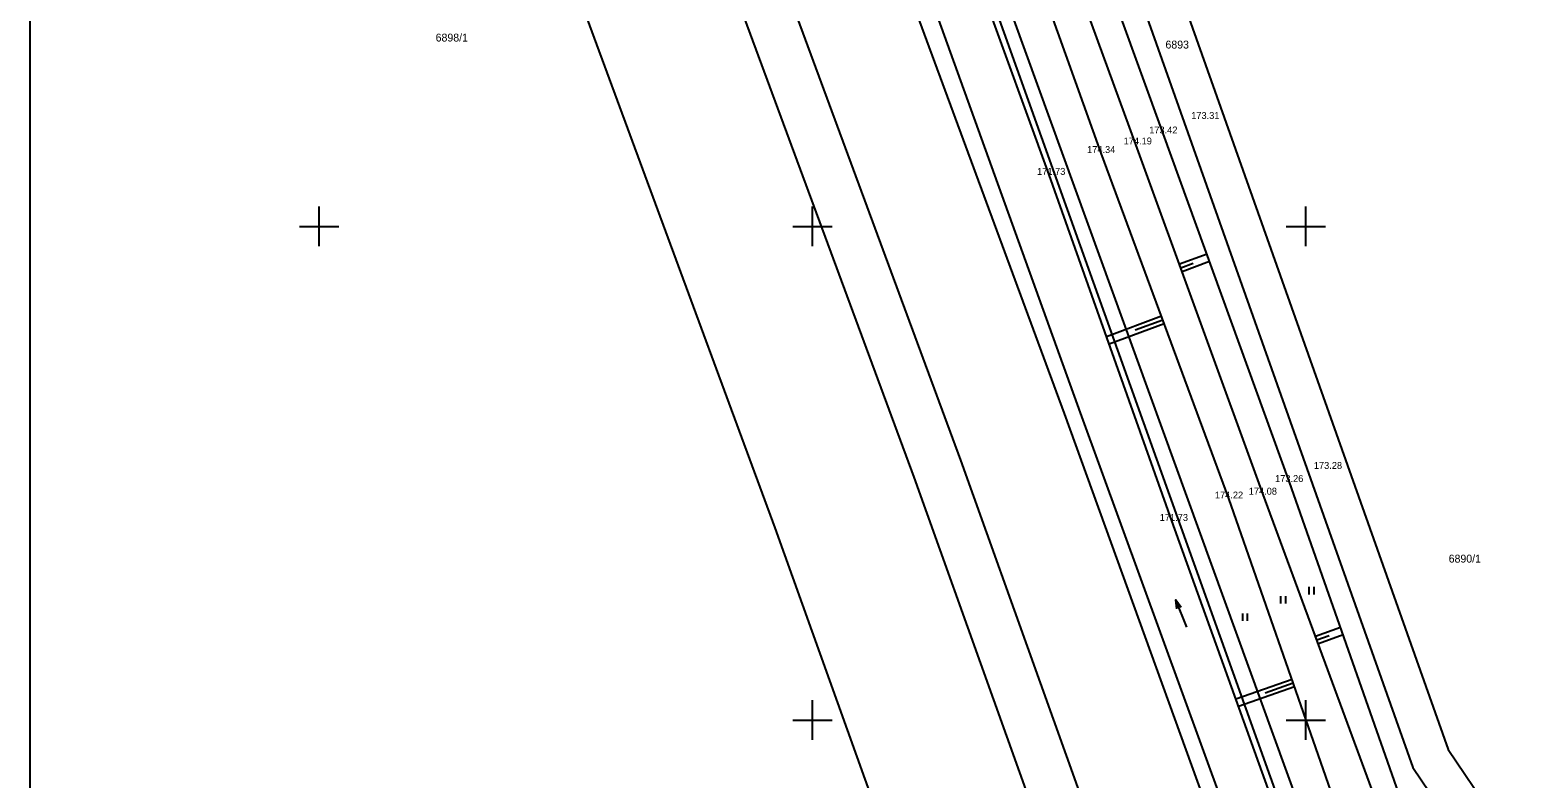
# Model space of a CAD drawing. Extents: x -612546 to -611926, y -1201932 to -1200444.
# Drawn here: x -612529.3 to -612376.5, y -1200656 to -1200580.1 of the extents above; entities that cross this region are included whole.
import ezdxf

# ---------------------------------------------------------------- set-up
doc = ezdxf.new("R2010")
doc.units = 0
for name, color, linetype in [('14 hrana pata svahu', 7, 'Continuous'), ('15 šrafy', 7, 'Continuous'), ('61 legenda křížky', 7, 'Continuous'), ('Hranice parcel', 7, 'Continuous'), ('Parcelní čísla', 7, 'Continuous'), ('Vnitřní kresba', 7, 'Continuous'), ('Vrstva 36', 7, 'Continuous'), ('Vrstva 45', 7, 'Continuous'), ('Vrstva 63', 7, 'Continuous'), ('výška bodu', 7, 'Continuous')]:
    doc.layers.add(name, color=color, linetype=linetype)

msp = doc.modelspace()

# ---------------------------------------------------------------- linework, layer by layer
at = {"layer": '14 hrana pata svahu'}
for points in [[(-612314.18, -1200875.11), (-612327.34, -1200838.97), (-612340.35, -1200802.82), (-612354.12, -1200765.43), (-612365.98, -1200732.87), (-612379.97, -1200693.65), (-612390.48, -1200664.58), (-612404.32, -1200627.17), (-612417.23, -1200591.7), (-612430.62, -1200555.12), (-612438.2, -1200533.09), (-612444.43, -1200520.21), (-612457.3, -1200503.64), (-612467.57, -1200490.07), (-612474.64, -1200478.9), (-612480.36, -1200469.57)], [(-612115.84, -1201111.42), (-612142.3, -1201080.92), (-612162.58, -1201054.92), (-612187.22, -1201025.94), (-612211.45, -1200996.73), (-612237.71, -1200968.13), (-612275.47, -1200925.26), (-612297.25, -1200898.18), (-612305.42, -1200888.34), (-612310.59, -1200874.11), (-612323.74, -1200837.38), (-612336.44, -1200801.43), (-612350.12, -1200764.09), (-612361.57, -1200731.35), (-612377.95, -1200692.77), (-612388.38, -1200663.69), (-612401.66, -1200625.89), (-612414.44, -1200590.59), (-612427.78, -1200553.92), (-612436.33, -1200532.1), (-612442.76, -1200519.02), (-612455.83, -1200502.43), (-612463.71, -1200487.36), (-612471.87, -1200478.15)], [(-612323.51, -1200877.98), (-612336.33, -1200841.94), (-612349.79, -1200805.31), (-612362.71, -1200767.78), (-612375.47, -1200735.58), (-612389.68, -1200697.07), (-612400.23, -1200666.93), (-612413.57, -1200629.83), (-612426, -1200594.78), (-612439.47, -1200557.74), (-612446.83, -1200536.72), (-612452.68, -1200524.51), (-612464.9, -1200509.43), (-612478.9, -1200492.91), (-612482.95, -1200488.23)], [(-612103.83, -1201136.8), (-612121.3, -1201116.23), (-612147.17, -1201085.43), (-612168.95, -1201059.31), (-612192.84, -1201031.05), (-612217.78, -1201001.78), (-612242.41, -1200972.81), (-612279.4, -1200929.44), (-612302.66, -1200902.78), (-612311.18, -1200891.48), (-612317.69, -1200875.87), (-612330.64, -1200840.25), (-612343.46, -1200803.61), (-612356.83, -1200766.41), (-612369.51, -1200733.46), (-612383.93, -1200694.82), (-612394.68, -1200665.1), (-612407.78, -1200627.56), (-612420.74, -1200592.57), (-612433.93, -1200555.79), (-612441.34, -1200534.1), (-612447.31, -1200522.04), (-612459.97, -1200505.78), (-612472.95, -1200489.44)]]:
    msp.add_lwpolyline(points, dxfattribs=at)
at = {"layer": '15 šrafy'}
for p, q in [((-612410.01, -1200602.82), (-612412.81, -1200603.84)), ((-612411.4, -1200603.75), (-612412.67, -1200604.22)), ((-612409.74, -1200603.57), (-612412.54, -1200604.59)), ((-612420.2, -1200611.14), (-612414.63, -1200609.07)), ((-612419.93, -1200611.89), (-612414.35, -1200609.82)), ((-612417.28, -1200610.48), (-612414.49, -1200609.45)), ((-612396.49, -1200640.61), (-612399, -1200641.54)), ((-612397.61, -1200641.46), (-612398.86, -1200641.92)), ((-612396.22, -1200641.37), (-612398.72, -1200642.29)), ((-612407.09, -1200647.85), (-612401.39, -1200645.86)), ((-612406.82, -1200648.6), (-612401.13, -1200646.61)), ((-612404.11, -1200647.23), (-612401.26, -1200646.24))]:
    msp.add_line(p, q, dxfattribs=at)
at = {"layer": '61 legenda křížky'}
for p, q in [((-612500, -1200602), (-612500, -1200598)), ((-612450, -1200602), (-612450, -1200598)), ((-612400, -1200602), (-612400, -1200598)), ((-612502, -1200600), (-612498, -1200600)), ((-612452, -1200600), (-612448, -1200600)), ((-612402, -1200600), (-612398, -1200600)), ((-612450, -1200652), (-612450, -1200648)), ((-612400, -1200652), (-612400, -1200648)), ((-612452, -1200650), (-612448, -1200650)), ((-612402, -1200650), (-612398, -1200650))]:
    msp.add_line(p, q, dxfattribs=at)
at = {"layer": 'Hranice parcel'}
for points in [[(-612492.54, -1200475.45), (-612489.15, -1200479.9), (-612487.29, -1200482.34), (-612470.55, -1200499.86), (-612454.58, -1200517.89), (-612449.12, -1200526.98), (-612444.88, -1200537.01), (-612400.71, -1200658.68), (-612382.76, -1200708.97), (-612320.94, -1200880.21), (-612316.28, -1200891.06), (-612307.37, -1200903.62), (-612259.67, -1200958.71), (-612214.29, -1201012.03), (-612172.62, -1201060.98), (-612120.7, -1201123.05), (-612073.85, -1201178.4), (-612068.4, -1201184.83), (-612055.42, -1201199.11), (-612044.78, -1201213.9), (-612040.42, -1201224.33), (-612036.87, -1201232.26)], [(-612053.63, -1201234.04), (-612049.72, -1201229.74), (-612051.31, -1201220.57), (-612058.28, -1201208.42), (-612073.89, -1201189.58), (-612079.31, -1201183.16), (-612173.25, -1201072.99), (-612266.53, -1200963.98), (-612308.11, -1200916.05), (-612320.05, -1200901.46), (-612326.37, -1200888.91), (-612352.76, -1200817.26), (-612383.45, -1200732.24), (-612424.46, -1200618.96), (-612450.75, -1200547.77), (-612455.75, -1200534.91), (-612462.05, -1200524.68), (-612490.01, -1200492.58), (-612497.19, -1200482.99)], [(-612467.57, -1200483.94), (-612457.95, -1200496.74), (-612450.95, -1200506.06), (-612439.8, -1200520.91), (-612432.5, -1200532.58), (-612389.16, -1200654.79), (-612379.73, -1200668.74)], [(-612504.85, -1200495.41), (-612492.66, -1200506.93), (-612476.27, -1200525), (-612462.43, -1200549.41), (-612435.01, -1200623.69), (-612394.62, -1200736.44), (-612362.83, -1200822.52), (-612336.91, -1200893.7), (-612329.46, -1200906.86), (-612317.29, -1200922.46), (-612274.72, -1200972.15), (-612181.97, -1201080.59), (-612092.56, -1201185.28), (-612096.16, -1201188.77)], [(-612098.55, -1201185.97), (-612185.77, -1201083.84), (-612278.52, -1200975.4), (-612321.16, -1200925.63), (-612333.63, -1200909.64), (-612341.47, -1200895.8), (-612367.52, -1200824.24), (-612399.32, -1200738.15), (-612439.71, -1200625.4), (-612466.98, -1200551.52), (-612480.35, -1200527.95), (-612496.23, -1200510.43), (-612507.54, -1200499.75)], [(-612424.14, -1200544.19), (-612385.56, -1200652.97), (-612376.97, -1200665.68), (-612365.31, -1200671.92), (-612359.59, -1200681.01), (-612363.6, -1200702.67), (-612362.5, -1200716.42), (-612304.9, -1200876.31), (-612299.88, -1200886.48), (-612289.63, -1200899.21), (-612225.19, -1200972.6)], [(-612480.63, -1200557.86), (-612453.81, -1200630.53), (-612413.42, -1200743.28), (-612381.61, -1200829.41), (-612355.13, -1200902.11), (-612346.14, -1200918), (-612332.78, -1200935.12), (-612289.91, -1200985.15), (-612197.17, -1201093.58), (-612109.96, -1201195.71)]]:
    msp.add_lwpolyline(points, dxfattribs=at)
at = {"layer": 'Vnitřní kresba'}
msp.add_line((-612445.86, -1200537.76), (-612402.12, -1200659.9), dxfattribs=at)
msp.add_lwpolyline([(-612077.99, -1201182.01), (-612172.2, -1201072.72), (-612264.55, -1200963.36), (-612306.48, -1200914.97), (-612319.15, -1200900.26), (-612324.5, -1200887.86), (-612350.35, -1200818.69), (-612381.6, -1200731.97), (-612422.84, -1200618.87), (-612449.81, -1200544.11), (-612465.28, -1200517.45), (-612482.79, -1200495.64), (-612497.19, -1200482.99)], dxfattribs=at)
at = {"layer": 'Vrstva 36'}
for p, q in [((-612402.52, -1200638.19), (-612402.52, -1200637.44)), ((-612402.02, -1200638.19), (-612402.02, -1200637.44)), ((-612399.66, -1200637.27), (-612399.66, -1200636.52)), ((-612399.16, -1200637.27), (-612399.16, -1200636.52)), ((-612406.39, -1200639.96), (-612406.39, -1200639.21)), ((-612405.89, -1200639.96), (-612405.89, -1200639.21))]:
    msp.add_line(p, q, dxfattribs=at)
at = {"layer": 'Vrstva 45'}
msp.add_line((-612412.07, -1200640.6), (-612413.18, -1200637.82), dxfattribs=at)
msp.add_lwpolyline([(-612413.07, -1200638.72), (-612413.18, -1200637.82), (-612412.64, -1200638.55)], dxfattribs=at)
at = {"layer": 'Vrstva 63'}
msp.add_line((-612529.3, -1200864.06), (-612529.3, -1200444.06), dxfattribs=at)

# ---------------------------------------------------------------- texts
at = {"layer": 'Parcelní čísla'}
for s, p in [('6898/1', (-612488.2, -1200581.28)), ('6893', (-612414.22, -1200581.99)), ('6890/1', (-612385.51, -1200634.05))]:
    msp.add_text(s, height=0.8, dxfattribs=at).set_placement(p)
at = {"layer": 'výška bodu'}
for s, p in [('173.31', (-612411.61, -1200589.12)), ('173.42', (-612415.87, -1200590.59)), ('174.19', (-612418.46, -1200591.7)), ('174.34', (-612422.17, -1200592.57)), ('171.73', (-612427.23, -1200594.78)), ('173.26', (-612403.11, -1200625.89)), ('173.28', (-612399.18, -1200624.56)), ('174.22', (-612409.21, -1200627.56)), ('174.08', (-612405.78, -1200627.17)), ('171.73', (-612414.8, -1200629.83))]:
    msp.add_text(s, height=0.7, dxfattribs=at).set_placement(p)

doc.saveas('drawing.dxf')
